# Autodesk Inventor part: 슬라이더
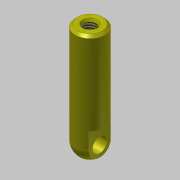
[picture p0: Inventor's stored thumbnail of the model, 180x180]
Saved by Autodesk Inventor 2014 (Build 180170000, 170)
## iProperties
Created: 2016-08
Part Number: 슬라이더
Material: 강철, 탄소
Document SubType Name: Modeling
Designer: mduedu
Density: 7.87 g/cm^3
Appearance: Yellow
Author: mduedu
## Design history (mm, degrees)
sketch "스케치1"
  geometry: C1 r 6 at (0, 0); 1 further point
  constraints: 1 centre point, 1 coincident
  dimensions: "d0" = 12 diameter of C1
extrude "돌출1" new body sketch "스케치1" distance "d1" = 47; taper "d2" = 0 deg
fillet "모깎기1" dims "d21" = 6
sketch "스케치6"
  geometry: L1 (6, 6)-(6, 47) reference; L2 (-6, 6)-(-6, 47) reference; L3 (6, 47)-(-6, 47) reference; L4 (0, 47)-(0, 0); L5 (6, 13)-(4, 13); L6 (4, 13)-(4, 0); L7 (4, 0)-(6, 0); L8 (6, 0)-(6, 13); L9 (-6, 13)-(-4, 13); L10 (-4, 13)-(-4, 0); L11 (-4, 0)-(-6, 0); L12 (-6, 0)-(-6, 13)
  constraints: 18 end point, 4 symmetric about line, 2 parallel, 2 perpendicular, 1 horizontal, 1 horizontal alignment, 1 midpoint, 1 point on line
  dimensions: "d22" = 13 distance of L7.end L5.start; "d24" = 4 distance between parallel lines of L6 L4
extrude "돌출5" cut sketch "스케치6" stored distance "d25" = 8; taper "d26" = 0 deg
sketch "스케치8"
  geometry: C1 r 3 at (6, 0); 1 further point
  constraints: 1 centre point, 1 horizontal alignment
  dimensions: "d27" = 6 diameter of C1; "d28" = 6 distance of point (0, 0) C1.centre
extrude "돌출6" cut sketch "스케치8" stored distance "d29" = 8; taper "d30" = 0 deg
hole "구멍1" diameter "d33" = 4.917; stored, may be unused: countersink angle "d37" = 90 deg, drill point angle "d39" = 118 deg; dims "d31" = 10, "d32" = 10, "d34" = 10, "d35" = 4, "d36" = 2, "d38" = 12
chamfer "모따기1" distance "d40" = 1; stored, may be unused: second distance "d41" = 2, angle "d42" = 30 deg
chamfer "모따기2" distance "d43" = 1; stored, may be unused: second distance "d44" = 2, angle "d45" = 30 deg
node "솔리드1"
